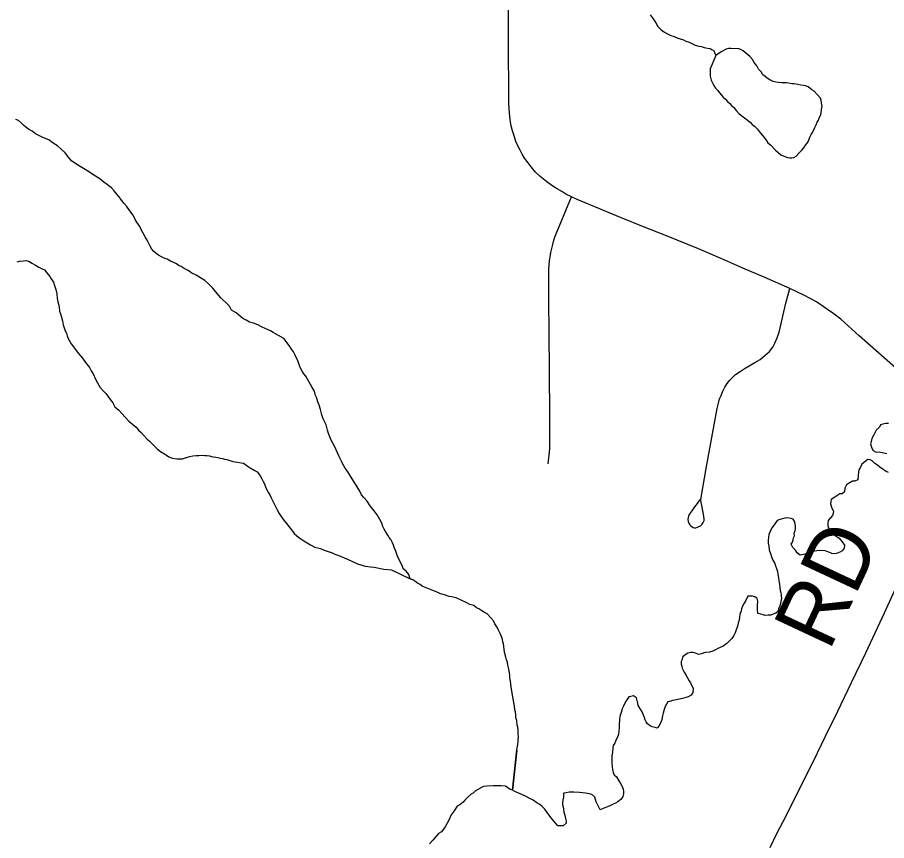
# Model space of a CAD drawing. Extents: x 103424 to 290657, y 38711 to 110967.
# Drawn here: x 149253 to 153409, y 64911 to 68847 of the extents above; entities that cross this region are included whole.
import ezdxf

# ---------------------------------------------------------------- set-up
doc = ezdxf.new("R2010")
doc.units = 0
for name, color, linetype in [('GM_X_County_Road', 7, 'Continuous'), ('GM_X_County_Road_Text', 7, 'Continuous'), ('GM_X_Minor_Lake', 7, 'Continuous'), ('GM_X_Minor_River', 7, 'Continuous'), ('GM_X_Township_Road', 7, 'Continuous')]:
    doc.layers.add(name, color=color, linetype=linetype)

msp = doc.modelspace()

# ---------------------------------------------------------------- linework, layer by layer
at = {"layer": 'GM_X_County_Road'}
for points in [[(153519.3, 67113.1), (153398.5, 67219.1), (153277.7, 67325.1), (153190.4, 67403.5), (153152.6, 67432.2), (153122.3, 67453.9), (153074.3, 67486.3), (153013.2, 67518.7), (152946.1, 67550.7), (152823.7, 67605.3), (152722.3, 67648.6), (152621, 67691.8), (152509.9, 67739.8), (152356.9, 67801.8), (152247.2, 67846.3), (152137.4, 67890.8), (152034.1, 67933.9), (151930.7, 67976.9), (151902.4, 67989), (151876.5, 68002.3), (151856, 68014.2), (151831.8, 68028.6), (151808.5, 68042.9), (151784.3, 68060.6), (151753.5, 68086.4), (151731.4, 68106.9), (151709.6, 68132.8), (151695.7, 68151.6), (151678.8, 68174.2), (151666.9, 68193.1), (151656.7, 68212.8), (151648.5, 68230), (151637.4, 68254.2), (151630, 68275.1), (151621, 68304.2), (151614.9, 68328.8), (151610.3, 68357.5), (151605.8, 68390), (151603.8, 68433.4), (151602.5, 68524.1), (151602.1, 68661.3), (151601.7, 68798.5), (151601.3, 68954.8)], [(152851.9, 64878), (152883.1, 64942.4), (152930.3, 65033), (152994.7, 65161.9), (153059.1, 65290.6), (153117.6, 65410), (153176, 65529.4), (153241.6, 65666.8), (153309.3, 65808.3), (153354.4, 65904.4), (153399.6, 66000.6), (153459, 66129.5)]]:
    msp.add_lwpolyline(points, dxfattribs=at)
at = {"layer": 'GM_X_Minor_Lake'}
for points in [[(153054.9, 68296.6), (153058.6, 68302.8), (153066.3, 68321.1), (153072.1, 68333.4), (153077.9, 68345.6), (153083.7, 68355.8), (153087.6, 68366), (153093.4, 68378.3), (153097.2, 68388.4), (153098.8, 68406.6), (153100.5, 68422.8), (153098.1, 68438.9), (153095.9, 68449), (153093.6, 68461), (153077.1, 68478.9), (153062.6, 68494.7), (153052.4, 68500.5), (153033.9, 68514.3), (153021.6, 68520.1), (153011.5, 68521.8), (152999.3, 68523.6), (152985.1, 68525.3), (152966.9, 68529), (152956.8, 68528.7), (152940.5, 68532.4), (152930.4, 68534.2), (152918.3, 68534), (152908.2, 68533.7), (152892, 68535.4), (152879.8, 68537.2), (152867.6, 68540.9), (152851.3, 68548.7), (152839, 68556.5), (152828.7, 68564.3), (152818.4, 68572.2), (152810, 68586.1), (152797.6, 68600), (152789.2, 68616), (152776.7, 68631.8), (152768.3, 68645.8), (152755.9, 68659.7), (152745.6, 68667.5), (152733.3, 68679.4), (152723, 68687.2), (152712.8, 68693), (152702.6, 68696.9), (152664.2, 68698), (152654.1, 68697.8), (152642, 68695.5), (152617.6, 68682.5), (152592.1, 68664.2)], [(152592.1, 68664.2), (152565.2, 68601), (152565.5, 68584.8), (152565.9, 68566.7), (152570.4, 68546.6), (152576.7, 68534.6), (152583.1, 68520.6), (152591.4, 68508.7), (152601.8, 68496.8), (152610, 68486.9), (152620.4, 68475), (152628.7, 68465.1), (152639, 68455.2), (152649.3, 68445.3), (152659.6, 68435.5), (152667.9, 68425.5), (152678.3, 68415.7), (152690.7, 68401.8), (152703.1, 68387.9), (152756.5, 68346.7), (152766.9, 68334.8), (152777.2, 68327), (152791.6, 68313.1), (152806.2, 68293.3), (152824.8, 68271.5), (152833.2, 68259.5), (152841.5, 68247.6), (152855.9, 68235.8), (152878.6, 68212.1), (152891, 68200.2), (152903.4, 68190.4), (152915.6, 68184.6), (152936, 68177), (152946.1, 68175.2), (152956.2, 68175.4), (152966.3, 68177.6), (152976.2, 68183.9), (152990.1, 68198.3), (153003.9, 68212.8), (153013.8, 68223.1), (153021.6, 68235.4), (153029.5, 68245.6), (153035.3, 68255.8), (153043, 68274.2), (153048.8, 68286.4), (153054.9, 68296.6)]]:
    msp.add_lwpolyline(points, dxfattribs=at)
at = {"layer": 'GM_X_Minor_River'}
for points in [[(152278.8, 68859.3), (152293.3, 68839.4), (152305.8, 68821.5), (152316.3, 68803.5), (152330.8, 68787.7), (152347.2, 68776), (152361.5, 68768.2), (152377.9, 68760.5), (152394.2, 68754.8), (152410.5, 68747), (152438.9, 68739.6), (152449.2, 68733.8), (152465.5, 68728), (152477.7, 68722.3), (152494, 68714.5), (152512.4, 68708.9), (152524.5, 68707.1), (152536.7, 68703.4), (152553, 68699.7), (152565.1, 68697.9), (152575.4, 68692.1)], [(152575.4, 68692.1), (152581.5, 68690.2), (152592.1, 68664.2)], [(149512.7, 68161), (149498.2, 68178.9), (149481.6, 68198.7), (149463.1, 68216.5), (149444.6, 68232.2), (149424, 68245.9), (149403.5, 68261.6), (149375, 68273.1), (149356.6, 68282.8), (149340.2, 68290.5), (149323.8, 68302.3), (149307.4, 68312), (149293.1, 68321.8), (149282.8, 68331.7), (149272.5, 68341.5), (149258.1, 68353.4), (149245.8, 68359.1)], [(150802.4, 66725.3), (150796.1, 66737.2), (150789.7, 66751.2), (150783.4, 66765.2), (150777, 66779.2), (150770.6, 66793.2), (150762.2, 66811.2), (150753.8, 66825.2), (150741, 66857.2), (150736.6, 66873.2), (150730, 66899.3), (150719.5, 66917.3), (150715.2, 66927.3), (150708.7, 66947.3), (150702.2, 66971.4), (150695.6, 66993.5), (150689.2, 67009.5), (150684.8, 67025.6), (150678.5, 67039.6), (150674, 67059.7), (150663.5, 67077.6), (150632.1, 67131.4), (150623.7, 67143.4), (150615.4, 67155.3), (150604.9, 67173.2), (150600.6, 67187.3), (150596.3, 67199.3), (150592, 67209.3), (150585.7, 67221.3), (150579.3, 67235.3), (150573, 67247.2), (150564.6, 67261.2), (150556.3, 67273.1), (150543.8, 67291), (150527.2, 67310.9), (150502.6, 67326.5), (150488.3, 67334.2), (150476.1, 67340), (150463.8, 67347.8), (150441.3, 67357.4), (150420.9, 67367.1), (150402.5, 67376.8), (150382.1, 67384.4), (150363.8, 67390.1), (150347.5, 67399.8), (150331.1, 67407.5), (150320.8, 67417.4), (150310.5, 67425.3), (150300.2, 67435.1), (150288, 67440.9), (150277.7, 67446.8), (150267.2, 67466.7), (150250.7, 67484.5), (150236.3, 67496.3), (150226, 67506.2), (150201.1, 67536), (150188.6, 67551.8), (150167.9, 67573.6), (150149.4, 67589.3), (150128.9, 67601), (150108.4, 67614.7), (150088, 67624.4), (150069.6, 67636.1), (150051.2, 67645.8), (150036.8, 67655.5), (150024.6, 67661.3), (150014.3, 67669.2), (150004.1, 67673), (149985.8, 67680.7), (149969.4, 67690.4), (149959.2, 67694.2), (149942.9, 67702), (149928.6, 67709.7), (149916.3, 67717.5), (149903.9, 67729.4), (149895.6, 67739.3), (149889.3, 67749.2), (149883, 67763.3), (149874.5, 67781.2), (149864.1, 67797.2), (149855.6, 67815.2), (149845.1, 67833.1), (149836.6, 67851.1), (149826.2, 67865), (149817.9, 67876.9), (149807.3, 67900.9), (149790.7, 67922.8), (149776.1, 67942.6), (149763.7, 67956.5), (149751.2, 67972.4), (149740.8, 67988.3), (149728.3, 68002.2), (149715.9, 68018.1), (149703.5, 68031.9), (149685, 68045.6), (149666.5, 68059.4), (149648, 68075.1), (149619.3, 68092.7), (149598.8, 68106.4), (149533.3, 68147.3), (149512.7, 68161)], [(149252.2, 67678.8), (149264.3, 67681.1), (149282.4, 67683.5), (149294.5, 67683.8), (149310.8, 67680.1), (149323.1, 67672.3), (149339.5, 67662.6), (149355.8, 67652.8), (149372.2, 67645.1), (149382.4, 67639.3), (149394.8, 67625.4), (149409.3, 67607.6), (149415.6, 67597.6), (149426.1, 67581.7), (149430.4, 67565.6), (149436.9, 67545.6), (149441.4, 67525.5), (149443.9, 67503.3), (149446.3, 67487.2), (149450.6, 67475.2), (149452.9, 67461.1), (149455.3, 67443), (149459.6, 67429), (149464, 67412.9), (149468.4, 67396.8), (149472.9, 67376.7), (149481.6, 67348.7), (149487.9, 67336.7), (149492.2, 67324.7), (149498.6, 67308.7), (149511.2, 67286.7), (149525.8, 67264.8), (149544.5, 67241), (149565.2, 67217.2), (149579.8, 67197.4), (149598.5, 67173.5), (149606.9, 67157.6), (149617.4, 67139.6), (149625.9, 67119.6), (149636.4, 67099.7), (149649, 67077.7)], [(149649, 67077.7), (149663.5, 67061.9), (149675.9, 67048), (149686.3, 67036.1), (149696.7, 67020.2), (149709.2, 67004.3), (149719.7, 66984.4), (149738.2, 66968.6), (149752.7, 66952.8), (149769.3, 66935), (149785.8, 66917.1), (149804.3, 66901.4), (149820.8, 66887.6), (149833.2, 66873.8), (149845.6, 66861.9), (149858, 66848.1), (149872.5, 66832.2), (149884.9, 66820.4), (149899.3, 66806.6), (149909.6, 66796.7), (149924.1, 66782.9), (149938.5, 66771.1), (149956.9, 66759.4), (149967.1, 66753.5), (149977.4, 66745.7), (149995.7, 66740), (150016, 66736.4), (150032.2, 66736.8), (150042.3, 66737), (150066.4, 66743.6), (150078.4, 66747.9), (150092.5, 66750.2), (150108.6, 66752.5), (150120.7, 66752.8), (150134.9, 66753.1), (150149.1, 66751.4), (150159.2, 66751.6), (150171.3, 66749.9), (150181.5, 66748.1), (150191.6, 66746.3), (150201.8, 66744.5), (150211.9, 66742.7), (150224.1, 66738.9), (150234.2, 66737.1), (150244.4, 66735.3), (150254.5, 66733.5), (150283, 66724), (150305.3, 66720.5), (150323.6, 66716.9), (150333.8, 66715.1), (150352.2, 66703.3), (150366.5, 66693.6), (150385, 66681.8), (150399.3, 66674.1), (150407.6, 66664.2), (150415.9, 66652.2), (150422.2, 66640.3), (150428.6, 66628.3), (150434.9, 66616.3), (150439.2, 66602.3), (150447.7, 66584.3), (150454, 66574.3), (150460.2, 66564.4), (150464.5, 66552.3), (150470.9, 66540.4), (150477.1, 66530.4), (150481.4, 66520.4), (150487.7, 66508.4), (150496.1, 66492.4), (150504.6, 66474.5), (150515, 66460.6), (150525.4, 66444.6), (150540, 66426.8), (150569, 66391.1), (150577.4, 66379.1), (150587.7, 66369.3), (150597.9, 66361.4), (150608.2, 66353.5), (150622.6, 66343.8), (150638.9, 66334), (150655.3, 66324.3), (150675.7, 66314.6), (150702.2, 66307.1), (150720.5, 66299.5), (150738.8, 66293.8), (150755.1, 66288.1), (150767.4, 66282.3), (150781.6, 66276.6), (150797.9, 66270.9), (150816.3, 66263.2), (150834.6, 66255.5), (150855, 66245.8), (150879.5, 66234.3), (150916.2, 66223), (150942.5, 66219.5), (150958.7, 66217.8), (151005.4, 66208.7), (151041.8, 66205.5), (151131.7, 66163)], [(153417.8, 66905.3), (153405.7, 66905), (153391.6, 66902.7), (153379.5, 66898.4), (153375.7, 66888.2), (153359.9, 66873.7), (153348.2, 66851.3), (153338.5, 66832.9), (153334.8, 66818.7), (153333, 66808.6), (153335.2, 66796.5), (153339.5, 66786.5), (153345.8, 66776.5), (153360.1, 66768.8), (153374.2, 66769.1), (153388.4, 66767.3), (153410.8, 66761.8)], [(151642.1, 65342.9), (151620.1, 65152), (151642.2, 65344.3), (151645.7, 65370.6), (151647.5, 65382.8), (151647.3, 65392.9), (151649, 65407), (151648.6, 65423.2), (151648.3, 65439.3), (151646, 65453.4), (151643.7, 65463.5), (151641.2, 65485.6), (151636.9, 65497.6), (151636.6, 65511.7), (151634.3, 65525.8), (151632.1, 65535.9), (151629.7, 65554), (151620.5, 65606.3), (151618, 65626.4), (151613.6, 65644.5), (151611, 65672.7), (151608.6, 65688.8), (151608.4, 65700.9), (151606.1, 65713), (151603.7, 65731.1), (151599.2, 65749.2), (151596.9, 65763.3), (151592.6, 65775.3), (151588.3, 65787.3), (151583.9, 65805.4), (151581.5, 65823.5), (151579.1, 65841.6), (151576.9, 65851.7), (151574.6, 65861.7), (151572.4, 65871.8), (151570.2, 65881.8), (151563.7, 65897.8), (151553.2, 65917.8), (151549, 65927.8), (151536.4, 65947.7), (151530.1, 65961.7), (151517.6, 65975.6), (151499, 65995.4), (151486.8, 66001.1), (151474.5, 66009), (151460.1, 66018.7), (151447.9, 66024.5), (151435.5, 66034.4), (151417.2, 66040), (151398.8, 66049.7), (151378.4, 66059.4), (151351.9, 66070.9), (151329.5, 66076.5), (151317.4, 66078.2), (151301.1, 66083.9), (151288.9, 66087.7), (151276.7, 66091.5), (151260.3, 66099.2), (151240, 66106.8), (151199.2, 66122.1), (151189, 66127.9), (151178.7, 66135.8), (151166.5, 66141.6), (151154.1, 66151.4), (151143.9, 66157.2), (151131.7, 66163), (151125.2, 66183.1), (151112.7, 66199), (151098.3, 66210.8), (151094.1, 66220.8), (151087.6, 66238.8), (151077.1, 66256.8), (151070.8, 66270.7), (151066.4, 66284.8), (151062.2, 66294.8), (151055.7, 66312.8), (151051.5, 66322.8), (151047.2, 66334.8), (151038.7, 66350.8), (151030.5, 66360.7), (151024.2, 66370.7), (151013.7, 66388.6), (151007.4, 66400.6), (151001.1, 66412.6), (150996.7, 66428.6), (150986.2, 66446.6), (150973.6, 66468.5), (150959, 66488.4), (150940.3, 66512.2), (150925.7, 66534.1), (150909.2, 66551.9), (150898.8, 66563.8), (150890.3, 66581.8), (150877.8, 66601.7), (150865.2, 66623.6), (150829.6, 66679.4), (150821.3, 66691.3), (150815, 66703.3), (150808.7, 66713.3), (150802.4, 66725.3)], [(153418.7, 66671.1), (153406.5, 66674.9), (153392.2, 66684.7), (153377.8, 66696.5), (153365.4, 66706.3), (153353.2, 66714.1), (153340.8, 66725.9), (153330.5, 66731.8), (153320.4, 66733.6), (153290.6, 66710.7), (153284.8, 66696.5), (153277, 66684.2), (153275.2, 66672), (153273.6, 66655.8), (153272, 66635.6), (153257.9, 66629.2), (153245.8, 66629), (153227.9, 66618.5), (153217.9, 66612.2), (153210.1, 66595.9), (153208.5, 66577.7), (153196.6, 66569.4), (153186.5, 66569.1), (153162.6, 66552.5), (153144.6, 66542), (153142.8, 66531.8), (153141, 66521.7), (153147.5, 66499.6), (153155.9, 66485.7), (153154.1, 66475.6), (153150.3, 66465.4), (153130.6, 66440.7), (153128.8, 66428.6), (153129.1, 66416.5), (153135.5, 66398.4), (153143.9, 66386.5), (153156.3, 66374.6), (153168.6, 66366.8), (153182.9, 66357), (153197.4, 66339.2), (153207.9, 66323.3), (153206.2, 66309.1), (153196.3, 66296.8), (153186.4, 66290.5), (153170.3, 66284.1), (153158.2, 66281.8), (153148.1, 66283.6), (153133.8, 66289.3), (153115.5, 66297)], [(153115.5, 66297), (153093.2, 66298.6), (153075.1, 66296.2), (153058.9, 66293.8), (153046.9, 66289.5), (153030.9, 66283.1), (153012.8, 66278.6), (152996.7, 66276.3), (152982.3, 66286.1), (152973.9, 66300), (152961.6, 66311.9), (152953.1, 66327.8), (152959, 66338), (152962.8, 66348.2), (152964.6, 66358.4), (152968.4, 66368.5), (152968.2, 66380.7), (152972, 66392.8), (152973.8, 66403), (152973.5, 66413.1), (152971.1, 66435.2), (152962.7, 66447.2), (152952.5, 66451), (152932.2, 66454.6), (152922.2, 66452.3), (152898.1, 66445.8), (152886, 66441.5), (152872.3, 66421), (152860.5, 66406.6), (152852.8, 66388.2), (152847, 66374), (152845.3, 66361.8), (152843.6, 66345.6), (152843.9, 66333.5), (152846.2, 66319.4), (152848.6, 66301.3), (152855, 66283.3), (152859.4, 66267.2), (152865.8, 66251.2), (152874.3, 66235.3), (152878.5, 66225.2), (152882.9, 66211.2), (152887.2, 66197.2), (152889.5, 66183.1), (152891.8, 66169), (152894.2, 66152.9), (152896.6, 66136.8), (152898.9, 66120.7), (152901.2, 66106.6), (152903.5, 66096.6), (152905.8, 66084.5), (152906.1, 66066.3), (152904.4, 66056.2), (152902.6, 66044.1), (152898.8, 66033.9), (152893, 66019.6), (152891.2, 66007.5), (152879.3, 65999.1), (152867.3, 65992.8), (152855.3, 65988.5), (152843.1, 65988.2), (152829, 65987.9), (152818.9, 65989.7), (152808.7, 65993.6), (152794.4, 65997.3), (152792, 66015.4), (152791.8, 66025.5), (152791.6, 66035.6), (152793.2, 66055.8), (152790.9, 66067.9), (152778.6, 66075.7), (152768.4, 66079.5), (152756.3, 66079.2), (152746.2, 66079), (152736.5, 66058.6), (152728.7, 66046.3), (152720.9, 66032), (152715.2, 66019.8), (152713.3, 66009.7), (152707.7, 65991.4), (152705.9, 65979.2), (152704.2, 65965), (152700.4, 65952.8), (152698.6, 65940.7), (152685.3, 65904), (152679.5, 65891.8), (152669.7, 65877.5), (152659.8, 65867.1), (152645.9, 65852.7), (152628, 65840.2), (152614, 65833.9), (152602, 65829.5), (152592, 65823.3), (152578, 65816.9), (152561.9, 65812.5), (152545.8, 65810.2), (152535.7, 65807.9), (152523.7, 65803.6), (152511.6, 65801.3), (152495.3, 65807), (152483.1, 65810.8)], [(152483.1, 65810.8), (152471, 65810.6), (152459, 65806.3), (152447, 65799.9), (152433.1, 65787.5), (152431.3, 65777.4), (152427.5, 65767.2), (152427.7, 65755.1), (152430, 65745), (152432.2, 65735), (152440.7, 65717), (152449.1, 65703.1), (152457.4, 65689.1), (152465.8, 65675.2), (152472.1, 65665.2), (152478.5, 65651.2), (152484.8, 65639.2), (152483.2, 65619), (152475.4, 65606.7), (152461.4, 65598.3), (152445.3, 65593.9), (152433.3, 65589.6), (152397, 65582.8), (152385, 65580.5), (152372.9, 65576.2), (152362.9, 65574), (152351.2, 65551.5), (152345.5, 65537.3), (152341.8, 65521), (152338, 65506.8), (152334.3, 65490.6), (152328.7, 65472.3), (152320.9, 65458), (152313, 65447.7), (152302.8, 65451.5), (152288.6, 65455.3), (152278.4, 65459.1), (152266.1, 65468.9), (152259.8, 65478.9), (152255.6, 65488.9), (152251.3, 65498.9), (152247, 65510.9), (152240.6, 65526.9), (152232.3, 65538.8), (152221.8, 65556.8), (152219.5, 65568.8), (152217.2, 65580.9), (152212.9, 65592.9), (152198.6, 65602.7), (152186.5, 65600.4), (152176.4, 65598.2), (152164.7, 65579.8), (152156.9, 65565.5), (152151.1, 65553.2), (152145.3, 65541), (152139.6, 65522.7), (152134, 65504.4), (152132.2, 65492.2), (152130.8, 65461.9), (152131, 65451.8), (152129.4, 65435.6), (152127.7, 65419.5), (152123.9, 65409.3), (152118.1, 65397), (152110.4, 65376.7), (152102.5, 65366.4), (152100.8, 65354.3), (152099.2, 65334), (152095.5, 65315.8), (152095.9, 65299.6), (152096.2, 65283.5), (152096.7, 65263.3), (152098.9, 65251.3), (152101.3, 65237.2), (152107.6, 65225.2), (152117.9, 65215.3), (152128.4, 65197.4), (152136.8, 65183.4), (152143, 65173.5), (152149.4, 65157.4), (152151.7, 65147.4), (152151.9, 65135.3), (152148.2, 65121.1), (152140.4, 65108.8), (152124.5, 65096.3), (152112.5, 65090), (152098.5, 65083.7), (152082.5, 65075.2), (152070.4, 65070.9), (152054.4, 65064.5), (152040.4, 65058.2), (152021.4, 65096.1), (152017.1, 65108.1), (152014.9, 65118.2), (152000.4, 65132), (151988.3, 65133.8), (151970, 65137.4), (151941.6, 65140.8), (151913.3, 65142.2), (151891.1, 65141.7), (151877, 65139.4)], [(151877, 65139.4), (151864.9, 65137.1), (151865.3, 65119), (151861.6, 65104.8), (151859.8, 65092.6), (151860, 65082.5), (151862.2, 65072.5), (151864.5, 65060.4), (151866.8, 65046.3), (151871.2, 65032.3), (151873.6, 65016.2), (151877.8, 65004.1), (151878.1, 64994.1), (151862.2, 64981.6), (151852.1, 64981.4), (151837.9, 64981.1), (151829.6, 64991), (151821.3, 65000.9), (151804.7, 65020.7), (151796.4, 65032.7), (151786, 65044.5), (151775.6, 65060.5), (151763.2, 65074.3), (151750.8, 65084.2), (151736.5, 65091.9), (151720.1, 65103.7), (151699.7, 65113.3), (151679.2, 65125), (151632.3, 65146.2), (151620.1, 65152), (151609.9, 65155.8), (151587.3, 65171.5), (151565, 65173), (151548.9, 65172.7), (151528.7, 65172.2), (151498.4, 65171.6), (151482.3, 65169.2), (151472.2, 65164.9), (151458.3, 65156.6), (151444.3, 65148.2), (151434.4, 65139.9), (151422.4, 65133.6), (151406.5, 65119.1), (151392.7, 65104.6), (151384.8, 65094.4), (151368.9, 65081.9), (151356.9, 65075.6), (151341.2, 65053), (151327.5, 65034.6), (151315.9, 65008.1), (151298.4, 64977.4), (151280.7, 64952.8), (151266.8, 64944.4), (151239.1, 64913.5), (151223.4, 64895)]]:
    msp.add_lwpolyline(points, dxfattribs=at)
at = {"layer": 'GM_X_Township_Road'}
for points in [[(151791.9, 66712.5), (151796.6, 66753.2), (151798.9, 66784.6), (151798.5, 66949.7), (151796.5, 67348.4), (151795.2, 67485.1), (151794, 67621.8), (151794.5, 67642.1), (151795.8, 67662.3), (151797.5, 67682.4), (151800.3, 67702.5), (151803.9, 67722.4), (151808.1, 67742.3), (151813.2, 67761.8), (151819, 67781.2), (151825.5, 67800.4), (151832.8, 67819.3), (151867.6, 67904.1), (151902.4, 67989)], [(152520.7, 66544.6), (152514.9, 66539.3), (152510.4, 66532.8), (152503.8, 66523.2), (152491, 66506.2), (152477.4, 66487.2), (152468.9, 66474.7), (152465.6, 66469.9), (152462.3, 66462.6), (152460.4, 66455.6), (152459.3, 66447.1), (152461.2, 66437.2), (152464.5, 66428), (152469.3, 66421.4), (152472.9, 66416.2), (152479.9, 66410.7), (152484.3, 66408.5), (152490.6, 66407), (152496.8, 66406.7), (152505.3, 66408.9), (152512.3, 66412.2), (152518.9, 66415.9), (152527.4, 66423.6), (152532.9, 66432.4), (152536.5, 66440.9), (152537.3, 66449.7), (152536.2, 66461.1), (152533.8, 66471.8), (152530.7, 66487.1), (152528.9, 66496), (152525.4, 66513.8), (152522.6, 66527.6), (152521.1, 66538.3), (152522.3, 66551.5), (152546.9, 66690.3), (152573.1, 66837.5), (152599.8, 66976.2), (152605.8, 67002.6), (152611.2, 67022.6), (152617.6, 67039.3), (152624.9, 67057), (152636, 67079.2), (152646.4, 67096), (152659.3, 67112.9), (152673.6, 67127.2), (152687.1, 67139.3), (152709.2, 67154.5), (152733.6, 67170.3), (152779.3, 67197.1), (152804.3, 67211.9), (152827.4, 67230), (152848.9, 67250.1), (152865.6, 67270.2), (152875.4, 67289.3), (152886.6, 67315.3), (152895, 67342.2), (152927.5, 67480.6), (152946.1, 67550.7)]]:
    msp.add_lwpolyline(points, dxfattribs=at)

# ---------------------------------------------------------------- texts
at = {"layer": 'GM_X_County_Road_Text'}
msp.add_text('RD', height=301.87, rotation=64.9257, dxfattribs=at).set_placement((153134.4, 65811.7))

doc.saveas('drawing.dxf')
